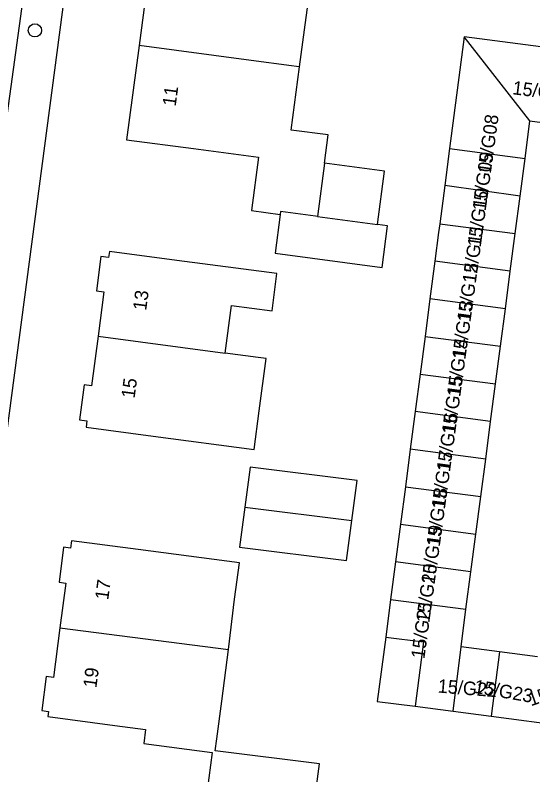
# Model space of a CAD drawing. Extents: x 161258 to 161838, y 380836 to 381727.
# Drawn here: x 161579.1 to 161617.4, y 381501.6 to 381557.9 of the extents above; entities that cross this region are included whole.
import ezdxf

# ---------------------------------------------------------------- set-up
doc = ezdxf.new("R2010")
doc.units = 0
for name, color, linetype in [('IMGEO_Boom', 7, 'Continuous'), ('IMGEO_Pand', 7, 'Continuous'), ('IMGEO_Pand_nummerreeks', 7, 'Continuous'), ('IMGEO_Rijbaan_lokaal_open', 7, 'Continuous'), ('IMGEO_Voetpad_open', 7, 'Continuous')]:
    doc.layers.add(name, color=color, linetype=linetype)

msp = doc.modelspace()

# ---------------------------------------------------------------- linework, layer by layer
at = {"layer": 'IMGEO_Boom'}
msp.add_circle((161580.536, 381556.793), 0.489, dxfattribs=at)
at = {"layer": 'IMGEO_Pand'}
for points in [[(161600.147, 381554.083), (161601.07, 381561.061), (161594.076, 381561.988), (161589.178, 381562.637), (161588.254, 381555.66)], [(161612.34, 381556.304), (161611.257, 381548.03)], [(161617.205, 381550.085), (161612.34, 381556.304)], [(161620.857, 381555.19), (161612.34, 381556.304)], [(161588.254, 381555.66), (161587.331, 381548.687), (161592.288, 381548.031), (161597.101, 381547.394), (161596.576, 381543.43), (161598.709, 381543.147)], [(161600.147, 381554.083), (161599.905, 381554.115), (161599.533, 381554.165), (161596.552, 381554.56), (161588.254, 381555.66)], [(161601.98, 381546.943), (161602.257, 381549.043), (161599.528, 381549.404), (161600.147, 381554.083)], [(161616.841, 381547.3), (161617.205, 381550.085)], [(161617.205, 381550.085), (161620.14, 381549.701)], [(161611.257, 381548.03), (161610.9, 381545.298)], [(161611.257, 381548.03), (161616.841, 381547.3)], [(161601.98, 381546.943), (161601.463, 381542.992)], [(161605.907, 381542.401), (161606.43, 381546.354), (161601.98, 381546.943)], [(161616.476, 381544.514), (161616.841, 381547.3)], [(161610.9, 381545.298), (161610.529, 381542.459)], [(161616.476, 381544.514), (161610.9, 381545.298)], [(161616.112, 381541.729), (161616.476, 381544.514)], [(161598.709, 381543.147), (161598.334, 381540.281), (161606.264, 381539.226), (161606.666, 381542.3), (161605.907, 381542.401)], [(161601.463, 381542.992), (161601.323, 381543.011), (161598.736, 381543.355), (161598.709, 381543.147)], [(161601.463, 381542.992), (161605.907, 381542.401)], [(161610.529, 381542.459), (161610.443, 381541.797), (161610.165, 381539.674)], [(161610.529, 381542.459), (161616.112, 381541.729)], [(161615.748, 381538.944), (161616.112, 381541.729)], [(161594.635, 381532.87), (161595.101, 381536.392), (161598.099, 381535.995), (161598.465, 381538.759), (161591.036, 381539.743), (161586.051, 381540.404), (161585.99, 381539.945), (161585.427, 381540.02), (161585.092, 381537.488), (161585.649, 381537.414), (161585.215, 381534.135)], [(161610.165, 381539.674), (161609.801, 381536.889)], [(161615.748, 381538.944), (161610.165, 381539.674)], [(161615.384, 381536.159), (161615.748, 381538.944)], [(161609.801, 381536.889), (161609.437, 381534.103)], [(161615.384, 381536.159), (161609.801, 381536.889)], [(161615.019, 381533.373), (161615.384, 381536.159)], [(161585.215, 381534.135), (161584.725, 381530.44), (161584.176, 381530.513), (161583.832, 381527.918), (161584.392, 381527.844), (161584.33, 381527.379), (161589.287, 381526.722), (161596.781, 381525.729), (161597.158, 381528.578), (161597.672, 381532.462), (161597.077, 381532.542), (161594.635, 381532.87)], [(161585.215, 381534.135), (161594.635, 381532.87)], [(161609.437, 381534.103), (161609.072, 381531.318)], [(161609.437, 381534.103), (161615.019, 381533.373)], [(161614.655, 381530.588), (161615.019, 381533.373)], [(161609.072, 381531.318), (161608.708, 381528.533)], [(161609.072, 381531.318), (161614.655, 381530.588)], [(161614.291, 381527.803), (161614.655, 381530.588)], [(161608.708, 381528.533), (161608.344, 381525.748)], [(161614.291, 381527.803), (161608.708, 381528.533)], [(161613.926, 381525.017), (161614.291, 381527.803)], [(161608.344, 381525.748), (161607.979, 381522.962)], [(161613.926, 381525.017), (161608.344, 381525.748)], [(161613.562, 381522.232), (161613.926, 381525.017)], [(161604.01, 381520.459), (161604.403, 381523.423), (161596.475, 381524.418), (161596.082, 381521.454)], [(161607.979, 381522.962), (161607.615, 381520.177)], [(161607.979, 381522.962), (161613.562, 381522.232)], [(161613.198, 381519.447), (161613.562, 381522.232)], [(161596.082, 381521.454), (161595.689, 381518.49), (161603.617, 381517.495), (161604.01, 381520.459)], [(161596.082, 381521.454), (161604.01, 381520.459)], [(161607.615, 381520.177), (161607.25, 381517.392)], [(161607.615, 381520.177), (161613.198, 381519.447)], [(161612.834, 381516.662), (161613.198, 381519.447)], [(161594.883, 381510.908), (161595.323, 381514.622), (161595.68, 381517.315), (161588.18, 381518.308), (161583.253, 381518.961), (161583.18, 381518.414), (161582.664, 381518.482), (161582.321, 381515.887), (161582.831, 381515.819), (161582.39, 381512.492)], [(161607.25, 381517.392), (161606.886, 381514.607)], [(161612.834, 381516.662), (161607.25, 381517.392)], [(161612.469, 381513.876), (161612.834, 381516.662)], [(161606.886, 381514.607), (161606.522, 381511.821)], [(161606.886, 381514.607), (161612.469, 381513.876)], [(161612.105, 381511.091), (161612.469, 381513.876)], [(161582.39, 381512.492), (161581.905, 381508.833), (161581.371, 381508.903), (161581.037, 381506.376), (161581.545, 381506.309), (161581.494, 381505.923), (161586.451, 381505.266), (161588.731, 381504.964), (161588.593, 381503.923), (161593.659, 381503.252), (161593.286, 381500.441)], [(161582.39, 381512.492), (161594.883, 381510.908)], [(161606.522, 381511.821), (161605.898, 381507.053), (161608.707, 381506.686)], [(161606.522, 381511.821), (161609.331, 381511.454), (161608.707, 381506.686)], [(161601.224, 381499.44), (161601.298, 381500), (161601.617, 381502.414), (161593.885, 381503.39), (161594.001, 381504.266), (161594.374, 381507.076), (161594.883, 381510.908)], [(161611.516, 381506.318), (161612.105, 381511.091)], [(161614.948, 381510.719), (161612.105, 381511.091)], [(161614.948, 381510.719), (161614.324, 381505.951)], [(161617.757, 381510.352), (161614.948, 381510.719)], [(161608.707, 381506.686), (161611.516, 381506.318)], [(161611.516, 381506.318), (161614.324, 381505.951)], [(161614.324, 381505.951), (161619.942, 381505.216)]]:
    msp.add_lwpolyline(points, dxfattribs=at)
at = {"layer": 'IMGEO_Rijbaan_lokaal_open'}
msp.add_lwpolyline([(161566.653, 381461.801), (161566.898, 381463.819), (161567.603, 381469.069), (161569.393, 381482.117), (161569.975, 381486.348), (161570.167, 381487.742), (161571.673, 381499.011), (161571.805, 381500), (161572.723, 381506.947), (161573.416, 381512.187), (161574.519, 381520.584), (161574.905, 381523.52), (161575.385, 381527.238), (161576.585, 381536.522), (161577.269, 381541.528), (161578.342, 381549.389), (161580.345, 381564.178), (161581.163, 381570.648), (161581.742, 381575.234), (161582.456, 381581.501), (161583.035, 381585.721), (161583.151, 381586.547)], dxfattribs=at)
at = {"layer": 'IMGEO_Voetpad_open'}
msp.add_lwpolyline([(161571.043, 381470.087), (161571.884, 381477.487), (161574.866, 381500), (161586.507, 381587.885)], dxfattribs=at)

# ---------------------------------------------------------------- texts
at = {"layer": 'IMGEO_Pand_nummerreeks'}
for s, rotation, p in [('15/G07', 352.8008, (161615.872, 381552.062)), ('11', 82.4601, (161590.963, 381551.128)), ('15/G08', 82.2143, (161614.302, 381546.145)), ('15/G09', 82.2143, (161613.921, 381543.363)), ('15/G10', 82.2143, (161613.555, 381540.685)), ('15/G11', 82.2143, (161613.19, 381538.016)), ('15/G12', 82.2143, (161612.795, 381535.125)), ('13', 82.4731, (161588.776, 381535.989)), ('15/G13', 82.2143, (161612.416, 381532.356)), ('15/G14', 82.2143, (161612.037, 381529.58)), ('15/G15', 82.2143, (161611.657, 381526.805)), ('15', 82.4715, (161587.916, 381529.476)), ('15/G16', 82.2143, (161611.278, 381524.03)), ('15/G17', 82.2143, (161610.898, 381521.255)), ('15/G18', 82.2143, (161610.519, 381518.482)), ('15/G19', 82.2143, (161610.139, 381515.701)), ('15/G20', 82.2143, (161609.748, 381512.841)), ('17', 82.3164, (161585.965, 381514.534)), ('15/G21', 82.2143, (161609.383, 381510.172)), ('19', 82.3164, (161585.086, 381508.015)), ('15/G22', 355.4261, (161610.351, 381507.709)), ('15/G23', 350.1342, (161613.007, 381507.696)), ('15/G24', 19.4143, (161617.271, 381506.678))]:
    msp.add_text(s, height=1, rotation=rotation, dxfattribs=at).set_placement(p)

doc.saveas('drawing.dxf')
